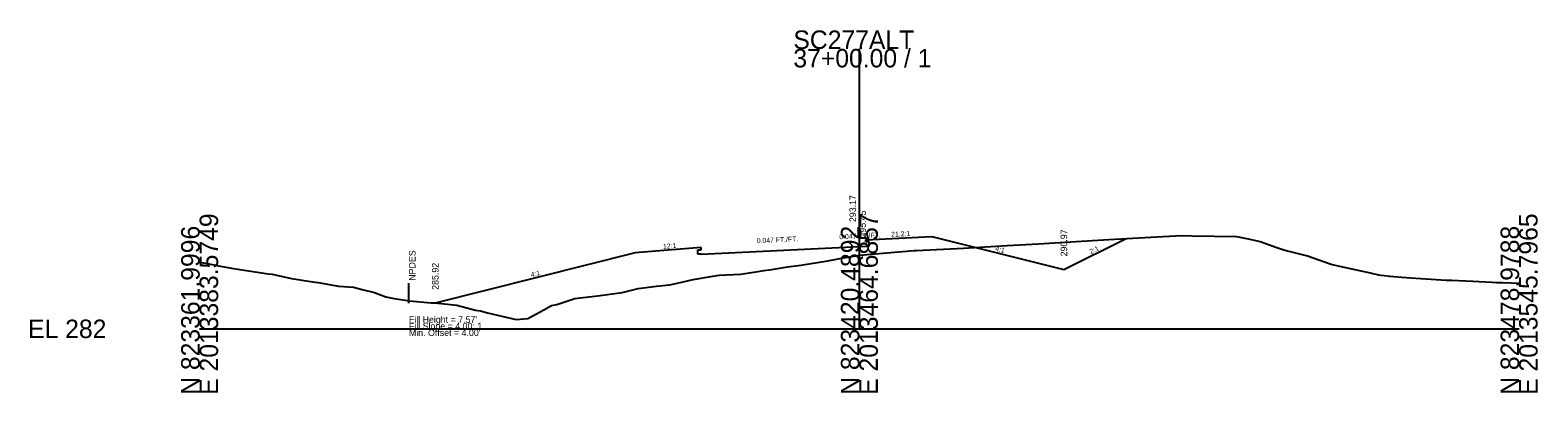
# Model space of a CAD drawing. Extents: x 205929 to 2357175, y -1785700 to 827636.
# Drawn here: x 2018394.5 to 2018623, y 825034.6 to 825089.5 of the extents above; entities that cross this region are included whole.
import ezdxf

# ---------------------------------------------------------------- set-up
doc = ezdxf.new("R2010")
doc.units = 0
for name, color, linetype in [('RD_GPK_XS_Cell', 7, 'Continuous'), ('RD_XS_Base', 7, 'Continuous'), ('RD_XS_EarthShd', 7, 'Continuous'), ('RD_XS_ExGround', 7, 'Continuous'), ('RD_XS_NPDES', 7, 'Continuous'), ('RD_XS_Pave', 7, 'Continuous'), ('RD_XS_TieSlope', 7, 'Continuous'), ('RD_XS_TX_Elev_EX', 7, 'Continuous'), ('RD_XS_TX_Elev_PR', 7, 'Continuous'), ('RD_XS_TX_ShdSlope', 7, 'Continuous'), ('RD_XS_TX_Slope', 7, 'Continuous'), ('RD_XS_TX_Warning', 7, 'Continuous')]:
    doc.layers.add(name, color=color, linetype=linetype)

msp = doc.modelspace()

# ---------------------------------------------------------------- linework, layer by layer
at = {"layer": 'RD_GPK_XS_Cell'}
for p, q in [((2018520.17, 825044.26), (2018520.17, 825086.66)), ((2018420.17, 825044.26), (2018520.17, 825044.26)), ((2018520.17, 825044.26), (2018620.17, 825044.26))]:
    msp.add_line(p, q, dxfattribs=at)
at = {"layer": 'RD_XS_Base'}
for p, q in [((2018496.17, 825055.58), (2018520.17, 825056.71)), ((2018520.17, 825056.71), (2018521.17, 825056.76))]:
    msp.add_line(p, q, dxfattribs=at)
at = {"layer": 'RD_XS_EarthShd'}
for p, q in [((2018521.17, 825057.76), (2018531.17, 825058.23)), ((2018496.17, 825056.58), (2018486.17, 825055.75))]:
    msp.add_line(p, q, dxfattribs=at)
at = {"layer": 'RD_XS_ExGround'}
msp.add_lwpolyline([(2018420.17, 825054.36), (2018421.05, 825054.2), (2018423.34, 825053.76), (2018424.99, 825053.47), (2018426.92, 825053.14), (2018429.59, 825052.75), (2018430.5, 825052.6), (2018431.15, 825052.52), (2018434.08, 825051.88), (2018437.32, 825051.38), (2018437.66, 825051.32), (2018438.14, 825051.26), (2018441.24, 825050.7), (2018443.48, 825050.58), (2018444.83, 825050.24), (2018446.69, 825049.74), (2018448.41, 825049.13), (2018449.64, 825048.87), (2018451.99, 825048.52), (2018455.24, 825048.19), (2018455.81, 825048.18), (2018459.15, 825047.84), (2018461.97, 825047.07), (2018462.73, 825046.97), (2018463.79, 825046.68), (2018468.14, 825045.67), (2018469.9, 825045.84), (2018472.34, 825047.12), (2018473.48, 825047.77), (2018474.3, 825047.96), (2018477.06, 825048.83), (2018480.89, 825049.31), (2018484.22, 825049.77), (2018486.63, 825050.35), (2018489.43, 825050.7), (2018491.39, 825050.94), (2018492.8, 825051.22), (2018494.97, 825051.72), (2018497.98, 825052.25), (2018498.55, 825052.34), (2018498.96, 825052.38), (2018502.13, 825052.53), (2018505.12, 825052.97), (2018505.71, 825053.08), (2018506.53, 825053.22), (2018509.3, 825053.65), (2018511.29, 825053.92), (2018512.88, 825054.14), (2018515.08, 825054.53), (2018516.46, 825054.78), (2018517.45, 825054.95), (2018520.17, 825055.43), (2018528.5, 825056.12), (2018528.83, 825056.13), (2018535.96, 825056.49), (2018542.58, 825056.88), (2018547.32, 825057.16), (2018552.18, 825057.45), (2018558.82, 825057.85), (2018559.9, 825057.91), (2018561.61, 825058), (2018566.17, 825058.25), (2018569.06, 825058.39), (2018570.64, 825058.37), (2018577.35, 825058.24), (2018579.1, 825057.89), (2018580.93, 825057.49), (2018583.47, 825056.59), (2018584.51, 825056.23), (2018585.26, 825056), (2018588.09, 825055.32), (2018591.67, 825054.06), (2018592.02, 825053.97), (2018595.25, 825053.26), (2018597.59, 825052.74), (2018598.84, 825052.45), (2018600.56, 825052.26), (2018602.42, 825052.08), (2018603.76, 825051.96), (2018609.11, 825051.65), (2018609.58, 825051.64), (2018609.92, 825051.62), (2018613.16, 825051.49), (2018616.08, 825051.34), (2018616.74, 825051.3), (2018617.66, 825051.27), (2018620.17, 825051.19)], dxfattribs=at)
at = {"layer": 'RD_XS_NPDES'}
msp.add_line((2018451.89, 825048.17), (2018451.89, 825051.17), dxfattribs=at)
at = {"layer": 'RD_XS_Pave'}
for p, q in [((2018521.17, 825057.43), (2018521.17, 825057.76)), ((2018495.67, 825056.23), (2018496.17, 825056.25)), ((2018495.67, 825055.56), (2018495.67, 825056.23)), ((2018496.17, 825055.58), (2018495.67, 825055.56)), ((2018496.17, 825056.25), (2018496.17, 825056.58)), ((2018521.67, 825057.45), (2018521.17, 825057.43)), ((2018521.17, 825056.76), (2018521.67, 825056.78)), ((2018521.67, 825056.78), (2018521.67, 825057.45))]:
    msp.add_line(p, q, dxfattribs=at)
at = {"layer": 'RD_XS_TieSlope'}
for p, q in [((2018531.17, 825058.23), (2018551.17, 825053.23)), ((2018551.17, 825053.23), (2018560.62, 825057.95)), ((2018486.17, 825055.75), (2018455.89, 825048.17))]:
    msp.add_line(p, q, dxfattribs=at)

# ---------------------------------------------------------------- texts
at = {"layer": 'RD_GPK_XS_Cell'}
for s, p in [('SC277ALT', (2018510.17, 825086.66)), ('37+00.00 / 1', (2018510.17, 825083.86)), ('EL 282', (2018394.17, 825042.86))]:
    msp.add_text(s, height=2.8, dxfattribs=at).set_placement(p)
for s, p in [('E 2013383.5749', (2018422.97, 825034.26)), ('E 2013464.6857', (2018522.97, 825034.26)), ('E 2013545.7965', (2018622.97, 825034.26)), ('N 823361.9996', (2018420.17, 825034.26)), ('N 823420.4892', (2018520.17, 825034.26)), ('N 823478.9788', (2018620.17, 825034.26))]:
    msp.add_text(s, height=2.8, rotation=90, dxfattribs=at).set_placement(p)
at = {"layer": 'RD_XS_TX_Elev_EX'}
msp.add_text('293.17', height=1, rotation=90, dxfattribs=at).set_placement((2018519.67, 825060.43))
at = {"layer": 'RD_XS_TX_Elev_PR'}
for s, p in [(' 295.45', (2018521.17, 825057.71)), ('290.97', (2018551.67, 825055.23)), ('285.92', (2018456.39, 825050.17))]:
    msp.add_text(s, height=1, rotation=90, dxfattribs=at).set_placement(p)
at = {"layer": 'RD_XS_TX_ShdSlope'}
for s, rotation, p in [('21.2:1', 2.6993, (2018525.01, 825058.19)), ('12:1', 4.7636, (2018490.44, 825056.35))]:
    msp.add_text(s, height=0.75, rotation=rotation, dxfattribs=at).set_placement(p)
at = {"layer": 'RD_XS_TX_Slope'}
for s, rotation, p in [('0.047 FT./FT.', 2.6993, (2018504.64, 825057.23)), ('0.047 FT./FT.', 2.6993, (2018517.14, 825057.82)), ('4:1', 345.9638, (2018540.72, 825056.1)), ('2:1', 26.5651, (2018555.28, 825055.56)), ('4:1', 14.0362, (2018470.46, 825052.07))]:
    msp.add_text(s, height=0.75, rotation=rotation, dxfattribs=at).set_placement(p)
at = {"layer": 'RD_XS_TX_Warning'}
msp.add_text(' NPDES', height=1, rotation=90, dxfattribs=at).set_placement((2018452.89, 825051.17))
for s, p in [("Fill Height = 7.57' ", (2018451.89, 825045.17)), ('Fill Slope = 4.00: 1', (2018451.89, 825044.17)), ("Min. Offset = 4.00' ", (2018451.89, 825043.17))]:
    msp.add_text(s, height=1, dxfattribs=at).set_placement(p)

doc.saveas('drawing.dxf')
